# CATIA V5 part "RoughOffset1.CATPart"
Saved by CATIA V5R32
Part number: Part2
Bounding box of the stored display mesh (mm): x -142.587 to 50, y -60 to 170, z -56 to 80
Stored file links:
  D:\PROJECTS\Project 2022\CATIA V5 6R 2022\Resources\Part Files\c17_catia_v6_6r2022_prt\RoughOffset1.CATPart
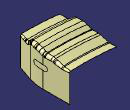
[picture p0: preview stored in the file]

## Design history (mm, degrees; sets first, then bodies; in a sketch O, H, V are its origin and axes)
Set1
  DatumSurface1
  DatumSurface2
  Sketch1 on xy-plane, origin (0, 0, 0), H (1, 0, 0), V (0, 1, 0)
    line L1 (180, 0) -> (420, 0)
    point P1 (180, 0)
    coincidence: P1 H
    horizontal: L1 H
  Point1: type OnPlane, Support xy-plane, H 200, V 5, Direction (1, 0, 0)
  Point2: type OnPlane, Support xy-plane, H 250, V 10, Direction (1, 0, 0)
  Point3: type OnPlane, Support xy-plane, H 320, V 13, Direction (1, 0, 0)
  Point4: type OnPlane, Support xy-plane, H 380, V 6, Direction (1, 0, 0)
  Point5: type OnPlane, Support xy-plane, H 400, V 5, Direction (1, 0, 0)
  LineCorner1: Elements (Point1; {linecornerpoint Pt Point2, Radius 60}; {linecornerpoint Pt Point3, Radius 55}; {linecornerpoint Pt Point4, Radius 80}; Point5)
  LawDistProj1: Reference Sketch1, Definition LineCorner1
  Intersect1: ToIntersect1 DatumSurface1, ToIntersect2 DatumSurface2
  CurvePar1: Length LawDistProj1, Offset Intersect1, Support DatumSurface1
  Point6: type OnCurve, Support Intersect1, Length 0
  Point7: type OnCurve, Support Intersect1, Length 48.6659 {= length(Intersect1) / 5}
  Point8: type OnCurve, Support Intersect1, Length 97.3318 {= (length(Intersect1)) * 2 / 5}
  Point9: type OnCurve, Support Intersect1, Length 145.9977 {= (length(Intersect1)) * 3 / 5}
  Point10: type OnCurve, Support Intersect1, Length 194.6636 {= (length(Intersect1)) * 4 / 5}
  Point11: type OnCurve, Support Intersect1, Length 243.3295 {= length(Intersect1)}
  Curve1: Elements (Point11; Point10; Point9; Point8; Point7; Point6)
  Fillet1: type BiTangent, Element1 DatumSurface2, Element2 DatumSurface1, Radius 25, Spine Curve1, HoldCurve CurvePar1
  Boundary1: Boundary Fillet1
  Split1: ToCut DatumSurface1, Cutting Boundary1
  Split2: ToCut DatumSurface2, Cutting Boundary1
  Join1: Elements (Split2; Fillet1; Split1)
  Offset1: Offset DatumSurface1, Length 20
  Offset2: Offset DatumSurface2, Length 20
  Trim1: Element1 Offset2, Element2 Offset1
  Fill1: Boundary ({fillboundary BoundaryWire edge of DatumSurface2, Support Join1}; {fillboundary BoundaryWire edge of DatumSurface2, Support Join1})
  Join2: Elements (Fill1; Join1)
Body1 (main body)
